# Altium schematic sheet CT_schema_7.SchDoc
size 318 x 188 mm
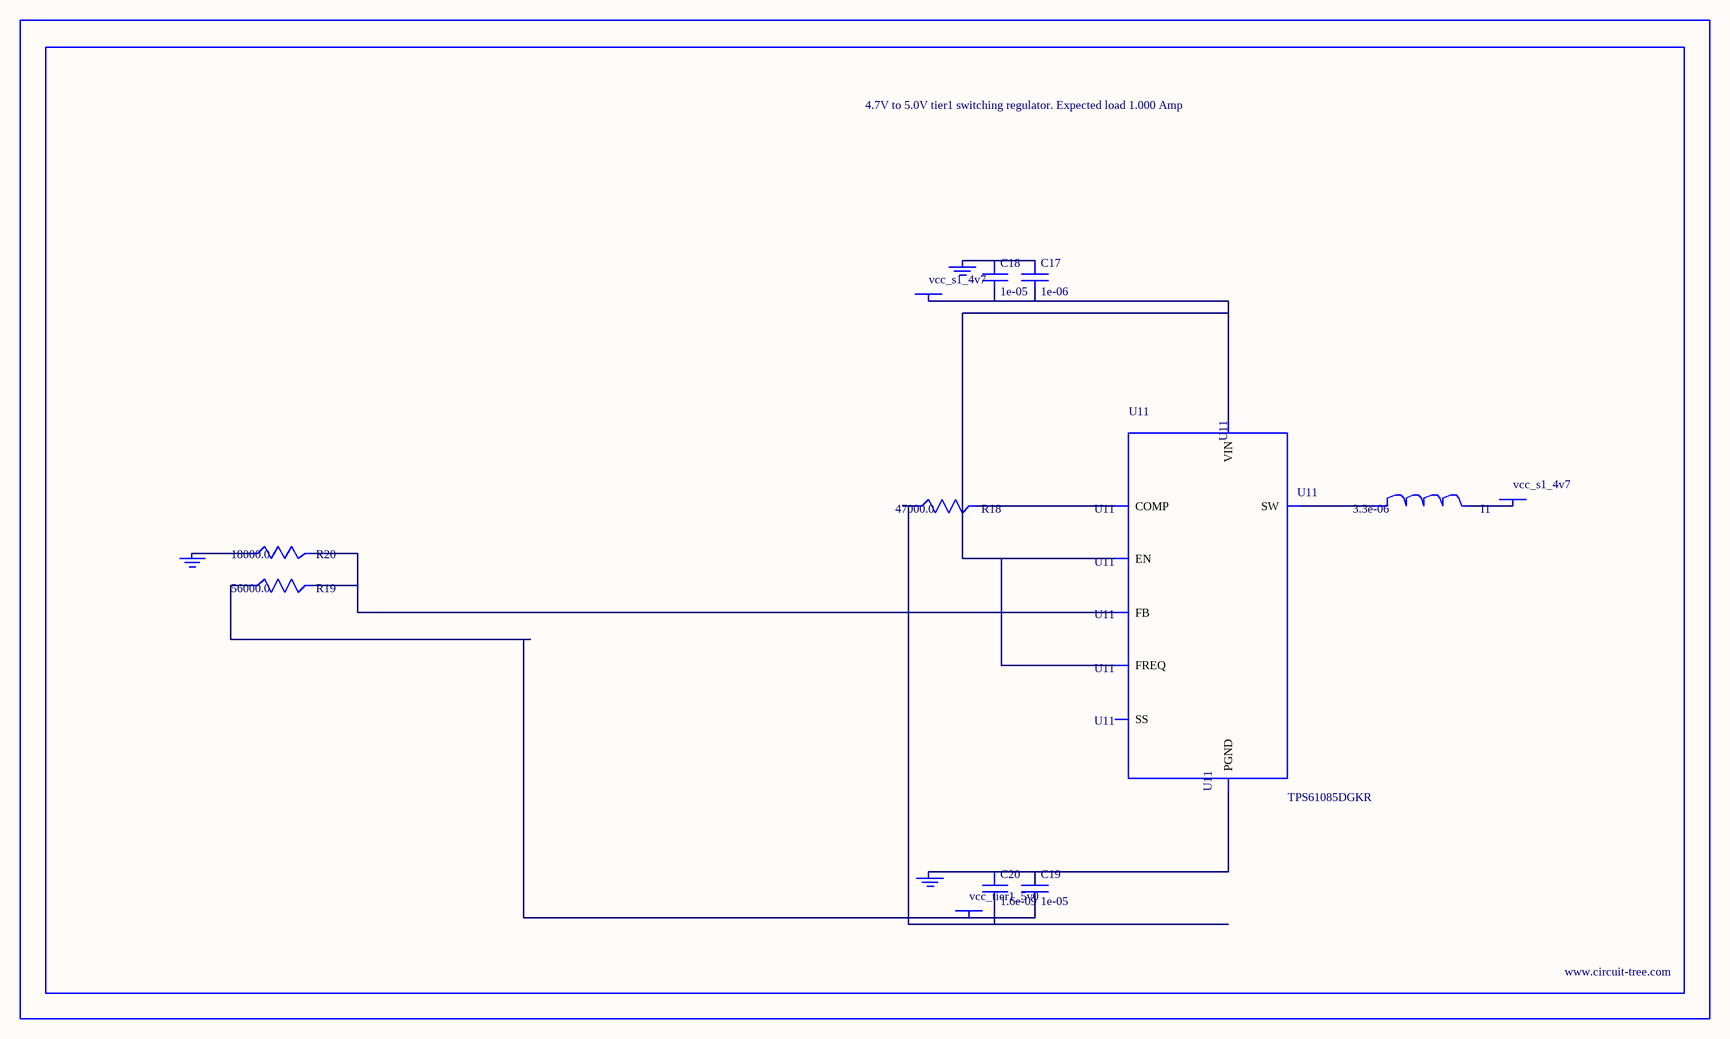
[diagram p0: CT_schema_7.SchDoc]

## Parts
BORDER6  (no value)
C17  1e-06  [C0603]
C18  1e-05  [C0805]
C19  1e-05  [C0805]
C20  1.6e-09  [C0603]
GND_INSTANCE_6_0  (no value)
GND_INSTANCE_6_1  (no value)
GND_INSTANCE_6_2  (no value)
I1  3.3e-06  [L0806]
POWER_INSTANCE_6_0  vcc_tier1_5v0
POWER_INSTANCE_6_1  vcc_s1_4v7
POWER_INSTANCE_6_2  vcc_s1_4v7
R18  47000.0  [R0603]
R19  56000.0  [R0603]
R20  18000.0  [R0603]
U11  TPS61085DGKR  [MSOP-8]

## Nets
NetC17_1: C17.1 C18.1 GND_INSTANCE_6_2.0(GND)
NetC17_2: C17.2 C18.2 POWER_INSTANCE_6_2.0(PWR) U11.3(EN) U11.6(VIN) U11.7(FREQ)
NetC19_1: C19.1 C20.1 GND_INSTANCE_6_1.0(GND) U11.4(PGND)
NetC19_2: C19.2 POWER_INSTANCE_6_0.0(PWR) R19.1
NetC20_2: C20.2 R18.1
NetGND_INSTANCE_6_0_0: GND_INSTANCE_6_0.0(GND) R20.1
NetI1_1: I1.1 U11.5(SW)
NetI1_2: I1.2 POWER_INSTANCE_6_1.0(PWR)
NetR18_2: R18.2 U11.1(COMP)
NetR19_2: R19.2 R20.2 U11.2(FB)

Not connected (* = marked no-connect by the designer): U11 8(SS)

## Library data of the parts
BORDER6 = BORDER_PAGE6
C17 = C0603C105K3RACTU
C18 C19 = C0805C106K8RACTU
C20 = 06035C162JAT2A
GND_INSTANCE_6_0-GND_INSTANCE_6_2 = GND
I1 = L0806C3R3MDWIT
POWER_INSTANCE_6_0-POWER_INSTANCE_6_2 = PWR
R18 = RC0603JR-0747KL
R19 = RC0603JR-0756KL
R20 = RC0603JR-0718KL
